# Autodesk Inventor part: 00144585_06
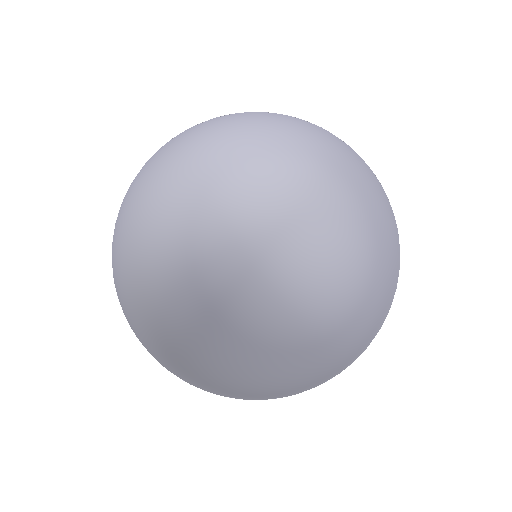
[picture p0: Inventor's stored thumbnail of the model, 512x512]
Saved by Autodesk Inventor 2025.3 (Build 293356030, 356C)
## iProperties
Created: 2021-02
Part Number: 00144585_06
Material: Generico
Document SubType Name: Modeling
Designer: R5800u
Density: 1 g/cm^3
Appearance: Default
Author: TraceParts
Sending System: SolidWorks 2021
Last Author: Albert
Last Saved: 2021-07-28
IsFastener: 1
TYPE: CATASM
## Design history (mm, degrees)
feature "Imported1"
node "Solido1"
